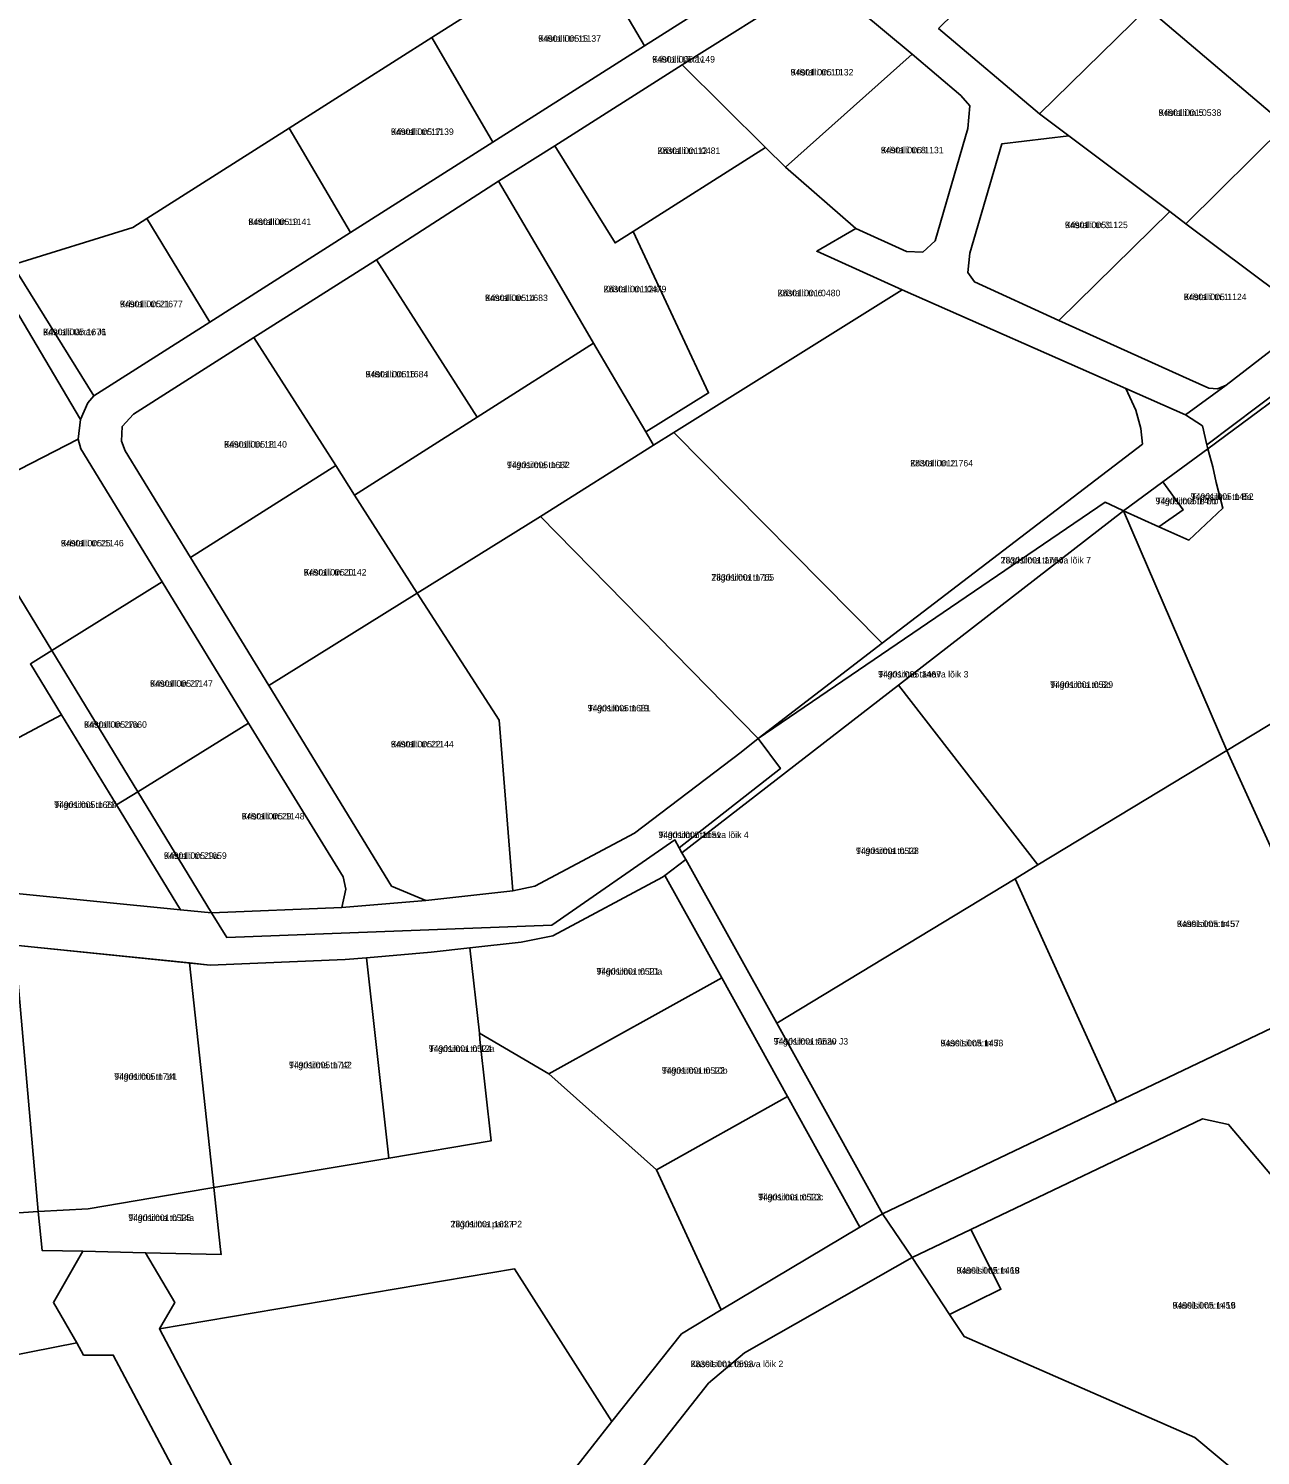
# Model space of a CAD drawing. Extents: x 647845 to 668483, y 6445298 to 6473683.
# Drawn here: x 655592.6 to 655877, y 6470382.6 to 6470712.1 of the extents above; entities that cross this region are included whole.
import ezdxf

# ---------------------------------------------------------------- set-up
doc = ezdxf.new("R2010")
doc.units = 0
for name, color, linetype in [('L_AADRESS', 7, 'Continuous'), ('PIIR', 7, 'Continuous'), ('TUNNUS', 7, 'Continuous')]:
    doc.layers.add(name, color=color, linetype=linetype)

msp = doc.modelspace()

# ---------------------------------------------------------------- linework, layer by layer
at = {"layer": 'PIIR'}
for points in [[(655412.92, 6470787.93), (655483.23, 6470815.62), (655692.58, 6470887.36), (655738.25, 6470830.73), (655784.98, 6470772.88), (655754, 6470753.36), (655720.68, 6470732.19), (655685.73, 6470710.01), (655652.81, 6470689.1), (655619.91, 6470668.18), (655616.71, 6470666.16), (655588.94, 6470657.53), (655584.3, 6470656.08), (655550.96, 6470646.26), (655545.46, 6470644.51), (655511.18, 6470633.78), (655367.08, 6470588.66)], [(655771.78, 6470721.43), (655743.54, 6470703.65), (655714.17, 6470684.96), (655701.14, 6470676.79), (655672.96, 6470658.69), (655644.67, 6470640.72), (655616.89, 6470623.05), (655614.24, 6470620.16), (655614.06, 6470616.81), (655614.94, 6470614.56), (655630, 6470589.9), (655648.14, 6470560.36), (655676.43, 6470514.07), (655684.38, 6470510.76), (655664.98, 6470509.12), (655665.86, 6470513.39), (655665.24, 6470516.18), (655643.39, 6470551.71), (655623.47, 6470584.33), (655604.69, 6470615.01), (655604.1, 6470617.24), (655604.63, 6470621.83), (655606.29, 6470625.64), (655607.69, 6470627.26), (655634.51, 6470644.3), (655666.97, 6470664.97), (655699.82, 6470685.82), (655734.81, 6470708.06), (655768.15, 6470729.2)], [(655802.72, 6470712.08), (655826.05, 6470692.4), (655832.81, 6470687.29), (655817.34, 6470685.47), (655809.92, 6470660.23), (655809.48, 6470655.7), (655811, 6470653.56), (655830.52, 6470644.66), (655860.64, 6470631), (655865.14, 6470629.05), (655867.13, 6470628.91), (655869.1, 6470629.72), (655859.72, 6470622.91), (655845.99, 6470628.97), (655794.33, 6470651.77), (655774.6, 6470660.66), (655783.59, 6470665.91), (655795.33, 6470660.62), (655799.07, 6470660.4), (655801.91, 6470663.08), (655809.48, 6470688.95), (655809.97, 6470694.18), (655807.83, 6470696.63), (655796.63, 6470706.11), (655778.41, 6470721.42)]]:
    msp.add_lwpolyline(points, dxfattribs=at)
for points in [[(655738.25, 6470830.73), (655767.23, 6470851.64), (655818.25, 6470786.79), (655892.58, 6470726.14), (655913.87, 6470716.85), (655928.34, 6470712.18), (655921.67, 6470664.11), (655922.99, 6470655.7), (655914.85, 6470662.52), (655882.8, 6470689.74), (655850.95, 6470716.76), (655827.67, 6470736.55), (655805.51, 6470755.54), (655784.98, 6470772.88)], [(655754, 6470753.36), (655768.15, 6470729.2), (655734.81, 6470708.06), (655720.68, 6470732.19)], [(655827.67, 6470736.55), (655850.95, 6470716.76), (655826.05, 6470692.4), (655802.72, 6470712.08)], [(655720.68, 6470732.19), (655734.81, 6470708.06), (655699.82, 6470685.82), (655685.73, 6470710.01)], [(655778.41, 6470721.42), (655796.63, 6470706.11), (655767.39, 6470680.06), (655762.76, 6470684.63), (655743.54, 6470703.65), (655771.78, 6470721.43), (655775.04, 6470722.4)], [(655826.05, 6470692.4), (655850.95, 6470716.76), (655882.8, 6470689.74), (655859.82, 6470667.01), (655856.11, 6470669.81), (655832.81, 6470687.29)], [(655685.73, 6470710.01), (655699.82, 6470685.82), (655666.97, 6470664.97), (655652.81, 6470689.1)], [(655796.63, 6470706.11), (655807.83, 6470696.63), (655809.97, 6470694.18), (655809.48, 6470688.95), (655801.91, 6470663.08), (655799.07, 6470660.4), (655795.33, 6470660.62), (655783.59, 6470665.91), (655767.39, 6470680.06)], [(655728.05, 6470662.55), (655714.17, 6470684.96), (655743.54, 6470703.65), (655762.76, 6470684.63), (655732.2, 6470665.21)], [(655859.82, 6470667.01), (655882.8, 6470689.74), (655914.85, 6470662.52), (655906.96, 6470659.05), (655889.08, 6470645.09)], [(655652.81, 6470689.1), (655666.97, 6470664.97), (655634.51, 6470644.3), (655619.91, 6470668.18)], [(655832.81, 6470687.29), (655856.11, 6470669.81), (655830.52, 6470644.66), (655811, 6470653.56), (655809.48, 6470655.7), (655809.92, 6470660.23), (655817.34, 6470685.47)], [(655723.08, 6470639.42), (655714.58, 6470653.98), (655701.14, 6470676.79), (655714.17, 6470684.96), (655728.05, 6470662.55), (655732.2, 6470665.21), (655743.1, 6470641.93), (655749.62, 6470627.95), (655735.16, 6470618.96), (655727.13, 6470632.46)], [(655743.1, 6470641.93), (655732.2, 6470665.21), (655762.76, 6470684.63), (655767.39, 6470680.06), (655783.59, 6470665.91), (655774.6, 6470660.66), (655794.33, 6470651.77), (655741.58, 6470618.78), (655736.94, 6470615.87), (655735.16, 6470618.96), (655749.62, 6470627.95)], [(655672.96, 6470658.69), (655701.14, 6470676.79), (655714.58, 6470653.98), (655723.08, 6470639.42), (655696.17, 6470622.32)], [(655856.11, 6470669.81), (655859.82, 6470667.01), (655889.08, 6470645.09), (655869.1, 6470629.72), (655867.13, 6470628.91), (655865.14, 6470629.05), (655860.64, 6470631), (655830.52, 6470644.66)], [(655634.51, 6470644.3), (655607.69, 6470627.26), (655588.94, 6470657.53), (655616.71, 6470666.16), (655619.91, 6470668.18)], [(655914.85, 6470662.52), (655922.99, 6470655.7), (655911.33, 6470651.73), (655894.27, 6470638.29), (655864.63, 6470615.93), (655863.63, 6470620.32), (655859.72, 6470622.91), (655869.1, 6470629.72), (655889.08, 6470645.09), (655906.96, 6470659.05)], [(655607.69, 6470627.26), (655606.29, 6470625.64), (655604.63, 6470621.83), (655584.3, 6470656.08), (655588.94, 6470657.53)], [(655644.67, 6470640.72), (655672.96, 6470658.69), (655696.17, 6470622.32), (655667.91, 6470604.34), (655663.55, 6470611.18)], [(655550.96, 6470646.26), (655584.3, 6470656.08), (655604.63, 6470621.83), (655604.1, 6470617.24), (655576.73, 6470603.28), (655568.88, 6470616.24)], [(655922.99, 6470655.7), (655912.16, 6470650.46), (655890.65, 6470634.11), (655864.87, 6470615.04), (655864.63, 6470615.93), (655894.27, 6470638.29), (655911.33, 6470651.73)], [(655741.58, 6470618.78), (655794.33, 6470651.77), (655845.99, 6470628.97), (655848.25, 6470623.93), (655849.42, 6470619.68), (655849.82, 6470616.13), (655789.71, 6470570.16)], [(655644.67, 6470640.72), (655663.55, 6470611.18), (655630, 6470589.9), (655614.94, 6470614.56), (655614.06, 6470616.81), (655614.24, 6470620.16), (655616.89, 6470623.05)], [(655736.94, 6470615.87), (655710.83, 6470599.43), (655682.39, 6470581.69), (655667.91, 6470604.34), (655696.17, 6470622.32), (655723.08, 6470639.42), (655727.13, 6470632.46), (655735.16, 6470618.96)], [(655890.65, 6470634.11), (655914.7, 6470572.84), (655869.25, 6470545.34), (655845.42, 6470600.72), (655853.57, 6470597.05), (655860.53, 6470593.91), (655868.36, 6470601.35), (655866.84, 6470607.27), (655866.04, 6470610.89), (655864.87, 6470615.04)], [(655848.25, 6470623.93), (655845.99, 6470628.97), (655859.72, 6470622.91), (655863.63, 6470620.32), (655864.63, 6470615.93), (655864.87, 6470615.04), (655854.51, 6470607.4), (655845.42, 6470600.72), (655843.66, 6470601.57), (655841.19, 6470602.73), (655761.11, 6470548.13), (655789.71, 6470570.16), (655849.82, 6470616.13), (655849.42, 6470619.68)], [(655576.73, 6470603.28), (655604.1, 6470617.24), (655604.69, 6470615.01), (655623.47, 6470584.33), (655597.98, 6470568.46), (655587.17, 6470586.3)], [(655761.11, 6470548.13), (655710.83, 6470599.43), (655736.94, 6470615.87), (655741.58, 6470618.78), (655789.71, 6470570.16)], [(655864.87, 6470615.04), (655866.04, 6470610.89), (655866.84, 6470607.27), (655868.36, 6470601.35), (655860.53, 6470593.91), (655853.57, 6470597.05), (655859.16, 6470600.9), (655854.51, 6470607.4)], [(655663.55, 6470611.18), (655667.91, 6470604.34), (655682.39, 6470581.69), (655648.14, 6470560.36), (655630, 6470589.9)], [(655854.51, 6470607.4), (655859.16, 6470600.9), (655853.57, 6470597.05), (655845.42, 6470600.72)], [(655841.19, 6470602.73), (655843.66, 6470601.57), (655845.42, 6470600.72), (655793.51, 6470560.48), (655743.45, 6470521.73), (655742.81, 6470522.9), (655766.21, 6470541.18), (655761.11, 6470548.13)], [(656088.38, 6470598.2), (656058.52, 6470559.43), (656035.65, 6470529.76), (656021.05, 6470525.76), (655973.08, 6470512.63), (655964.65, 6470508.6), (655918.64, 6470486.62), (655882.85, 6470469.5), (655881.63, 6470460.39), (655919.65, 6470415.18), (655928.62, 6470409.46), (655922.02, 6470404.59), (655915.42, 6470399.73), (655911.5, 6470409.34), (655869.7, 6470459.04), (655863.66, 6470460.34), (655810.16, 6470434.78), (655796.62, 6470428.31), (655789.8, 6470438.36), (655843.82, 6470464.17), (655895.08, 6470488.66), (655968.88, 6470523.92), (656028.6, 6470540.27), (656076.53, 6470602.47)], [(655825.68, 6470518.94), (655793.51, 6470560.48), (655845.42, 6470600.72), (655869.25, 6470545.34)], [(655761.11, 6470548.13), (655757.18, 6470545.02), (655732.49, 6470526.26), (655709.54, 6470514.03), (655704.45, 6470512.98), (655701.31, 6470552.4), (655682.39, 6470581.69), (655710.83, 6470599.43)], [(655942.81, 6470589.87), (655967.78, 6470526.71), (655968.88, 6470523.92), (655895.08, 6470488.66), (655869.25, 6470545.34), (655914.7, 6470572.84)], [(655569.44, 6470537.3), (655551.27, 6470567.22), (655587.17, 6470586.3), (655597.98, 6470568.46), (655593.05, 6470565.38), (655600.23, 6470553.6)], [(655623.47, 6470584.33), (655643.39, 6470551.71), (655617.84, 6470535.8), (655597.98, 6470568.46)], [(655682.39, 6470581.69), (655701.31, 6470552.4), (655704.45, 6470512.98), (655684.38, 6470510.76), (655676.43, 6470514.07), (655648.14, 6470560.36)], [(655617.84, 6470535.8), (655612.9, 6470532.83), (655600.23, 6470553.6), (655593.05, 6470565.38), (655597.98, 6470568.46)], [(655744.38, 6470520.2), (655743.45, 6470521.73), (655793.51, 6470560.48), (655825.68, 6470518.94), (655820.41, 6470515.77), (655765.4, 6470482.43)], [(655627.69, 6470508.58), (655589.08, 6470512.46), (655584.57, 6470514.46), (655581.38, 6470517.61), (655569.44, 6470537.3), (655600.23, 6470553.6), (655612.9, 6470532.83)], [(655643.39, 6470551.71), (655665.24, 6470516.18), (655665.86, 6470513.39), (655664.98, 6470509.12), (655634.89, 6470507.85), (655617.84, 6470535.8)], [(655761.11, 6470548.13), (655766.21, 6470541.18), (655742.81, 6470522.9), (655741.87, 6470524.72), (655713.46, 6470505.07), (655638.42, 6470502.18), (655634.89, 6470507.85), (655664.98, 6470509.12), (655684.38, 6470510.76), (655704.45, 6470512.98), (655709.54, 6470514.03), (655732.49, 6470526.26), (655757.18, 6470545.02)], [(655869.25, 6470545.34), (655895.08, 6470488.66), (655843.82, 6470464.17), (655820.41, 6470515.77), (655825.68, 6470518.94)], [(655634.89, 6470507.85), (655627.69, 6470508.58), (655612.9, 6470532.83), (655617.84, 6470535.8)], [(655634.56, 6470495.82), (655589.43, 6470500.46), (655515.32, 6470498.12), (655514.25, 6470510.04), (655520.76, 6470510.28), (655564.52, 6470511.7), (655589.08, 6470512.46), (655627.69, 6470508.58), (655634.89, 6470507.85), (655638.42, 6470502.18), (655713.46, 6470505.07), (655741.87, 6470524.72), (655742.81, 6470522.9), (655743.45, 6470521.73), (655744.38, 6470520.2), (655739.56, 6470516.54), (655738.96, 6470516.11), (655713.68, 6470502.61), (655706.34, 6470501.12), (655694.52, 6470499.83), (655685.55, 6470498.81), (655670.68, 6470497.51), (655665.74, 6470497.14)], [(655752.72, 6470492.9), (655739.56, 6470516.54), (655744.38, 6470520.2), (655765.4, 6470482.43), (655789.8, 6470438.36), (655784.58, 6470435.32), (655767.83, 6470465.47)], [(655738.96, 6470516.11), (655739.56, 6470516.54), (655752.72, 6470492.9), (655712.76, 6470470.72), (655696.72, 6470480.1), (655694.52, 6470499.83), (655706.34, 6470501.12), (655713.68, 6470502.61)], [(655820.41, 6470515.77), (655843.82, 6470464.17), (655789.8, 6470438.36), (655765.4, 6470482.43)], [(655515.32, 6470498.12), (655589.43, 6470500.46), (655594.88, 6470438.95), (655521.19, 6470433.93)], [(655589.43, 6470500.46), (655629.76, 6470496.32), (655635.42, 6470444.49), (655628.58, 6470443.32), (655606.39, 6470439.56), (655594.88, 6470438.95)], [(655685.55, 6470498.81), (655694.52, 6470499.83), (655696.72, 6470480.1), (655696.85, 6470478.62), (655699.41, 6470455.22), (655675.79, 6470451.26), (655675.24, 6470456.08), (655670.68, 6470497.51)], [(655635.42, 6470444.49), (655629.76, 6470496.32), (655634.56, 6470495.82), (655665.74, 6470497.14), (655670.68, 6470497.51), (655675.24, 6470456.08), (655675.79, 6470451.26)], [(655712.76, 6470470.72), (655752.72, 6470492.9), (655767.83, 6470465.47), (655737.59, 6470448.57)], [(655626.37, 6470417.89), (655619.67, 6470429.4), (655637.1, 6470429), (655636.98, 6470430.12), (655635.42, 6470444.49), (655675.79, 6470451.26), (655699.41, 6470455.22), (655696.85, 6470478.62), (655696.72, 6470480.1), (655712.76, 6470470.72), (655737.59, 6470448.57), (655752.5, 6470416.2), (655743.39, 6470410.72), (655727.33, 6470390.43), (655704.84, 6470425.67), (655622.86, 6470411.85)], [(655737.59, 6470448.57), (655767.83, 6470465.47), (655784.58, 6470435.32), (655752.5, 6470416.2)], [(655869.7, 6470459.04), (655911.5, 6470409.34), (655915.42, 6470399.73), (655878.72, 6470372.7), (655861.87, 6470386.73), (655808.61, 6470410.09), (655805.28, 6470415.17), (655817.14, 6470420.99), (655810.16, 6470434.78), (655863.66, 6470460.34)], [(655594.88, 6470438.95), (655606.39, 6470439.56), (655628.58, 6470443.32), (655635.42, 6470444.49), (655636.98, 6470430.12), (655637.1, 6470429), (655619.67, 6470429.4), (655605.2, 6470429.74), (655595.74, 6470429.95)], [(655603.77, 6470408.63), (655495.95, 6470387.34), (655468.5, 6470430.14), (655469.4, 6470430.23), (655521.19, 6470433.93), (655594.88, 6470438.95), (655595.74, 6470429.95), (655605.2, 6470429.74), (655598.36, 6470417.91)], [(655694.33, 6470348.42), (655727.33, 6470390.43), (655743.39, 6470410.72), (655752.5, 6470416.2), (655784.58, 6470435.32), (655789.8, 6470438.36), (655796.62, 6470428.31), (655757.9, 6470406.27), (655749.65, 6470399.31), (655712.22, 6470351.78)], [(655810.16, 6470434.78), (655817.14, 6470420.99), (655805.28, 6470415.17), (655796.62, 6470428.31)], [(655603.77, 6470408.63), (655598.36, 6470417.91), (655605.2, 6470429.74), (655619.67, 6470429.4), (655626.37, 6470417.89), (655622.86, 6470411.85), (655671.17, 6470320.11), (655675.72, 6470316.96), (655680.42, 6470316.26), (655683.59, 6470318.75), (655671.28, 6470298.18), (655672.38, 6470302.93), (655669.73, 6470307.02), (655660.58, 6470314.47), (655649.74, 6470334.92), (655626.92, 6470377.86), (655612.19, 6470405.76), (655605.35, 6470405.77)], [(655712.22, 6470351.78), (655749.65, 6470399.31), (655757.9, 6470406.27), (655796.62, 6470428.31), (655805.28, 6470415.17), (655808.61, 6470410.09), (655861.87, 6470386.73), (655878.72, 6470372.7), (655895.95, 6470358.42), (655936.36, 6470351.01), (655964.72, 6470333.18), (655902.62, 6470248.73), (655887.27, 6470265.04), (655895.68, 6470302.64), (655851.21, 6470343.02), (655721.12, 6470353.37)], [(655683.59, 6470318.75), (655680.42, 6470316.26), (655675.72, 6470316.96), (655671.17, 6470320.11), (655622.86, 6470411.85), (655704.84, 6470425.67), (655727.33, 6470390.43), (655694.33, 6470348.42), (655693.82, 6470342.1)], [(655520.92, 6470348.21), (655495.95, 6470387.34), (655603.77, 6470408.63), (655605.35, 6470405.77), (655612.19, 6470405.76), (655626.92, 6470377.86), (655535.64, 6470324.89)]]:
    msp.add_lwpolyline(points, close=True, dxfattribs=at)

# ---------------------------------------------------------------- texts
at = {"layer": 'L_AADRESS'}
for s, p in [('Kristalli tn 15', (655710.29, 6470709.01)), ('Kristalli tänav', (655736.6, 6470704.21)), ('Kristalli tn 10', (655768.57, 6470701.23)), ('Kristalli tn 5', (655853.5, 6470691.89)), ('Kristalli tn 17', (655676.3, 6470687.49)), ('Kristalli tn 12', (655737.84, 6470683.1)), ('Kristalli tn 8', (655789.39, 6470683.25)), ('Kristalli tn 19', (655643.38, 6470666.7)), ('Kristalli tn 3', (655831.91, 6470665.98)), ('Kristalli tn 14', (655698.02, 6470649.14)), ('Kristalli tn 12a', (655725.38, 6470651.16)), ('Kristalli tn 6', (655765.55, 6470650.25)), ('Kristalli tn 1', (655859.34, 6470649.36)), ('Kristalli tn 21', (655613.72, 6470647.72)), ('Kristalli tänav J1', (655595.99, 6470641.26)), ('Kristalli tn 16', (655670.42, 6470631.51)), ('Kristalli tn 18', (655637.78, 6470615.31)), ('Tiigrisilma tn 17', (655703.09, 6470610.56)), ('Kristalli tn 2', (655796.19, 6470610.96)), ('Tiigrisilma tn 8b', (655852.84, 6470602.23)), ('Tiigrisilma tn 8a', (655860.96, 6470603.24)), ('Kristalli tn 25', (655600.1, 6470592.49)), ('Kristalli tn 20', (655656.16, 6470585.77)), ('Tiigrisilma tänava lõik 7', (655817.07, 6470588.55)), ('Tiigrisilma tn 15', (655750.27, 6470584.6)), ('Kristalli tn 27', (655620.68, 6470560.08)), ('Tiigrisilma tänava lõik 3', (655788.78, 6470562.23)), ('Tiigrisilma tn 8c', (655828.51, 6470559.83)), ('Tiigrisilma tn 19', (655721.75, 6470554.41)), ('Kristalli tn 27a', (655605.45, 6470550.62)), ('Kristalli tn 22', (655676.3, 6470546.09)), ('Tiigrisilma tn 21', (655598.56, 6470532.11)), ('Kristalli tn 29', (655641.85, 6470529.45)), ('Tiigrisilma tänava lõik 4', (655738.06, 6470525.15)), ('Kristalli tn 29a', (655623.89, 6470520.34)), ('Tiigrisilma tn 10', (655783.67, 6470521.46)), ('Kassisilma tn 5', (655857.74, 6470504.6)), ('Tiigrisilma tn 10a', (655723.76, 6470493.63)), ('Tiigrisilma tänav J3', (655764.68, 6470477.46)), ('Kassisilma tn 7', (655803.17, 6470477.07)), ('Tiigrisilma tn 12a', (655685.04, 6470475.79)), ('Tiigrisilma tn 12', (655652.77, 6470472)), ('Tiigrisilma tn 10b', (655738.86, 6470470.74)), ('Tiigrisilma tn 14', (655612.43, 6470469.34)), ('Tiigrisilma tn 10c', (655761.09, 6470441.51)), ('Tiigrisilma tn 14a', (655615.68, 6470436.74)), ('Tiigrisilma park P2', (655690.07, 6470435.27)), ('Kassisilma tn 18', (655806.88, 6470424.58)), ('Kassisilma tn 16', (655856.75, 6470416.52)), ('Kassisilma tänava lõik 2', (655745.47, 6470402.99))]:
    msp.add_text(s, height=1.5, dxfattribs=at).set_placement(p)
at = {"layer": 'TUNNUS'}
for s, p in [('94901:005:1137', (655710.29, 6470709.01)), ('94901:005:1149', (655736.6, 6470704.21)), ('94901:005:1132', (655768.57, 6470701.23)), ('94901:001:0538', (655853.5, 6470691.89)), ('94901:005:1139', (655676.3, 6470687.49)), ('28301:001:0481', (655737.84, 6470683.1)), ('94901:005:1131', (655789.39, 6470683.25)), ('94901:005:1141', (655643.38, 6470666.7)), ('94901:005:1125', (655831.91, 6470665.98)), ('94901:005:1683', (655698.02, 6470649.14)), ('28301:001:0479', (655725.38, 6470651.16)), ('28301:001:0480', (655765.55, 6470650.25)), ('94901:005:1124', (655859.34, 6470649.36)), ('94901:005:1677', (655613.72, 6470647.72)), ('94901:005:1676', (655595.99, 6470641.26)), ('94901:005:1684', (655670.42, 6470631.51)), ('94901:005:1140', (655637.78, 6470615.31)), ('94901:005:1682', (655703.09, 6470610.56)), ('28301:001:1764', (655796.19, 6470610.96)), ('94901:005:1470', (655852.84, 6470602.23)), ('94901:005:1452', (655860.96, 6470603.24)), ('94901:005:1146', (655600.1, 6470592.49)), ('94901:005:1142', (655656.16, 6470585.77)), ('28301:001:1766', (655817.07, 6470588.55)), ('28301:001:1765', (655750.27, 6470584.6)), ('94901:005:1147', (655620.68, 6470560.08)), ('94901:005:1467', (655788.78, 6470562.23)), ('94901:001:0529', (655828.51, 6470559.83)), ('94901:005:1681', (655721.75, 6470554.41)), ('94901:005:1660', (655605.45, 6470550.62)), ('94901:005:1144', (655676.3, 6470546.09)), ('94901:005:1664', (655598.56, 6470532.11)), ('94901:005:1148', (655641.85, 6470529.45)), ('94901:005:1151', (655738.06, 6470525.15)), ('94901:005:1659', (655623.89, 6470520.34)), ('94901:001:0528', (655783.67, 6470521.46)), ('94901:005:1457', (655857.74, 6470504.6)), ('94901:001:0521', (655723.76, 6470493.63)), ('94901:001:0520', (655764.68, 6470477.46)), ('94901:005:1458', (655803.17, 6470477.07)), ('94901:001:0524', (655685.04, 6470475.79)), ('94901:005:1742', (655652.77, 6470472)), ('94901:001:0522', (655738.86, 6470470.74)), ('94901:005:1741', (655612.43, 6470469.34)), ('94901:001:0523', (655761.09, 6470441.51)), ('94901:001:0525', (655615.68, 6470436.74)), ('28301:001:1627', (655690.07, 6470435.27)), ('94901:005:1469', (655806.88, 6470424.58)), ('94901:005:1459', (655856.75, 6470416.52)), ('28301:001:0593', (655745.47, 6470402.99))]:
    msp.add_text(s, height=1.5, dxfattribs=at).set_placement(p)

doc.saveas('drawing.dxf')
